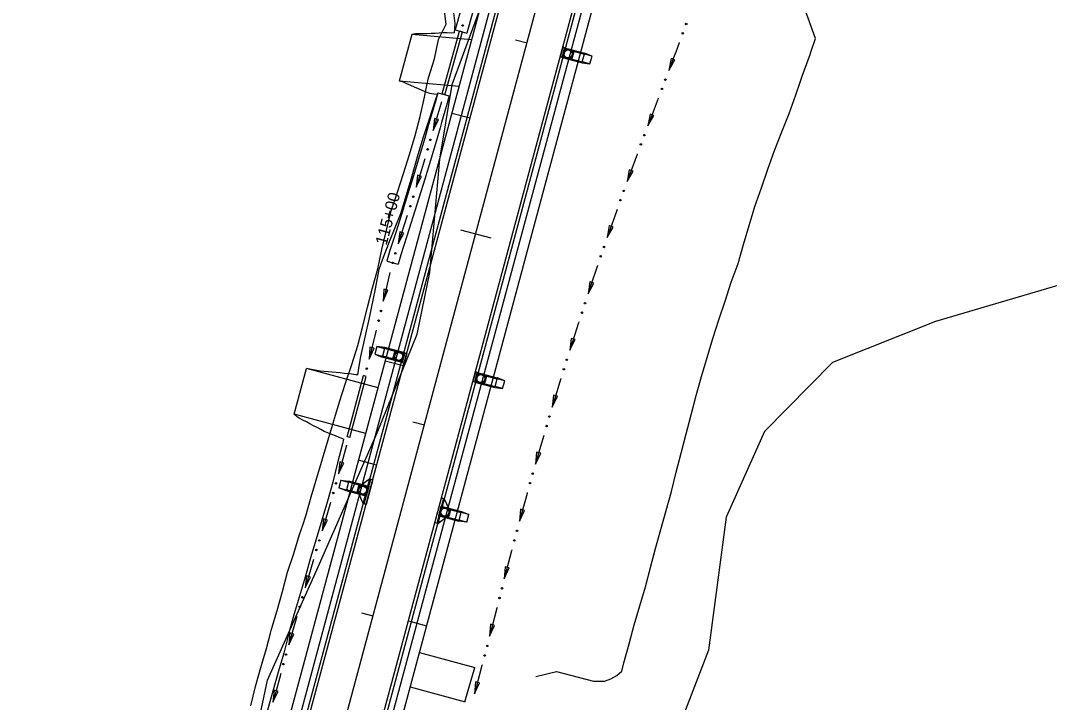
# Model space of a CAD drawing. Extents: x 979959 to 994833, y 1835619 to 1845316.
# Drawn here: x 992410 to 992930, y 1840093 to 1840438 of the extents above; entities that cross this region are included whole.
import ezdxf

# ---------------------------------------------------------------- set-up
doc = ezdxf.new("R2010")
doc.units = 0
for name, color, linetype in [('43', 7, 'Continuous'), ('Future 5 Lane Construction Limits', 7, 'Continuous'), ('R_Drainage', 7, 'Continuous'), ('R_Drainage Structure', 7, 'Continuous'), ('R_Horz Alg', 7, 'Continuous'), ('R_Horz Alg Stationing', 7, 'Continuous'), ('R_Proposed Const Limits', 7, 'Continuous'), ('R_Proposed Road', 7, 'Continuous'), ('R_Special Ditch', 7, 'Continuous')]:
    doc.layers.add(name, color=color, linetype=linetype)

msp = doc.modelspace()

# ---------------------------------------------------------------- linework, layer by layer
at = {"layer": '43'}
for points in [[(992621.79, 1840368.15), (992628.07, 1840405.79), (992643.68, 1840448.4), (992668.29, 1840487.44), (992720.39, 1840550.23), (992730.06, 1840577.03), (992737.54, 1840627.9), (992738.03, 1840675.61), (992735.39, 1840714.93), (992711.35, 1840789.79), (992657.1, 1840913.35), (992616.01, 1840968.75), (992554.37, 1841054.01), (992492.51, 1841112.85), (992422.69, 1841167.63), (992343.9, 1841218.47), (992195.05, 1841300.3), (992123.04, 1841334.73), (992016.5, 1841376.04), (991968.17, 1841403.44), (991911.14, 1841449.18)], [(993347.55, 1840512.83), (993212.6, 1840462.54), (993168.76, 1840438.22), (993078.36, 1840362.89), (993023.88, 1840330.57), (992872.5, 1840286.06), (992820.37, 1840265.31), (992785.96, 1840230.34), (992766.58, 1840187.1), (992757.72, 1840119.83), (992738.11, 1840069.09)], [(992517.56, 1840024.39), (992534.47, 1840104.68), (992560.81, 1840163.53), (992590.06, 1840229.67), (992610.27, 1840279.68), (992616.63, 1840310.73), (992621.79, 1840368.15)]]:
    msp.add_lwpolyline(points, dxfattribs=at)
at = {"layer": 'Future 5 Lane Construction Limits'}
for points in [[(992624.94, 1840436.39), (992624.94, 1840436.42), (992623.68, 1840446.93), (992623.26, 1840461.03), (992634.83, 1840462.41)], [(992526.13, 1840091.74), (992528.55, 1840101.44), (992531.16, 1840111.1), (992533.99, 1840120.69), (992536.1, 1840128.48), (992536.48, 1840129.88), (992536.61, 1840130.34), (992536.65, 1840130.5), (992536.78, 1840130.97), (992539.38, 1840139.95), (992542.13, 1840149.57), (992544.71, 1840159.23), (992547.79, 1840168.75), (992550.81, 1840178.3), (992552.36, 1840183.11), (992553.87, 1840187.83), (992556.68, 1840197.43), (992559.57, 1840207.01), (992562.44, 1840216.59), (992565.2, 1840226.2), (992568.07, 1840235.79), (992571.02, 1840245.35), (992574.07, 1840254.88), (992577.26, 1840264.38), (992580.29, 1840273.92), (992582.71, 1840283.63), (992585.12, 1840293.33), (992587.76, 1840302.98), (992590.34, 1840312.64), (992592.41, 1840322.44), (992594.73, 1840332.17), (992597.04, 1840341.91), (992600.27, 1840351.39), (992603.36, 1840360.92), (992606.33, 1840370.47), (992609.3, 1840380.03), (992611.77, 1840389.72), (992614, 1840399.48), (992614.69, 1840402.96), (992615.93, 1840409.31), (992619.07, 1840418.82), (992620.92, 1840427.77), (992621.1, 1840428.63), (992624.94, 1840436.39)]]:
    msp.add_lwpolyline(points, dxfattribs=at)
at = {"layer": 'R_Drainage'}
for p, q in [((992629.57, 1840433.49), (992635.35, 1840431.89)), ((992683.59, 1840419.58), (992684.88, 1840424.41)), ((992685.37, 1840424.28), (992683.92, 1840424.67)), ((992684.2, 1840419.93), (992685.24, 1840423.79)), ((992684.88, 1840424.41), (992695.02, 1840421.68)), ((992685.24, 1840423.79), (992694.89, 1840421.19)), ((992683.59, 1840419.58), (992693.72, 1840416.85)), ((992684.2, 1840419.93), (992693.85, 1840417.33)), ((992689.71, 1840423.11), (992688.41, 1840418.28)), ((992693.85, 1840417.33), (992694.89, 1840421.19)), ((992698.76, 1840420.15), (992694.89, 1840421.19)), ((992698.76, 1840420.15), (992695.02, 1840421.67)), ((992697.72, 1840416.29), (992698.76, 1840420.15)), ((992693.72, 1840416.85), (992697.72, 1840416.29)), ((992697.72, 1840416.29), (992693.85, 1840417.33)), ((992620.72, 1840401.7), (992626.5, 1840400.1)), ((992594.95, 1840316.58), (992600.74, 1840315.02)), ((992589.88, 1840273.41), (992588.84, 1840269.55)), ((992593.87, 1840272.85), (992589.88, 1840273.41)), ((992589.88, 1840273.41), (992593.74, 1840272.37)), ((992593.74, 1840272.37), (992592.7, 1840268.51)), ((992603.4, 1840269.77), (992593.74, 1840272.37)), ((992604.01, 1840270.13), (992593.87, 1840272.85)), ((992588.84, 1840269.55), (992592.57, 1840268.03)), ((992588.84, 1840269.55), (992592.7, 1840268.51)), ((992602.71, 1840265.3), (992592.57, 1840268.03)), ((992602.36, 1840265.91), (992592.7, 1840268.51)), ((992597.88, 1840266.6), (992599.18, 1840271.43)), ((992603.4, 1840269.77), (992602.36, 1840265.91)), ((992604.01, 1840270.13), (992602.71, 1840265.3)), ((992602.23, 1840265.43), (992603.67, 1840265.04)), ((992639.4, 1840255.42), (992640.7, 1840260.25)), ((992641.18, 1840260.12), (992639.74, 1840260.51)), ((992640.01, 1840255.77), (992641.05, 1840259.64)), ((992640.7, 1840260.25), (992650.84, 1840257.52)), ((992641.05, 1840259.64), (992650.71, 1840257.04)), ((992645.53, 1840258.95), (992644.23, 1840254.12)), ((992649.67, 1840253.17), (992650.71, 1840257.04)), ((992654.57, 1840256), (992650.71, 1840257.04)), ((992654.57, 1840256), (992650.84, 1840257.52)), ((992639.4, 1840255.42), (992649.54, 1840252.69)), ((992640.01, 1840255.77), (992649.67, 1840253.17)), ((992649.54, 1840252.69), (992653.53, 1840252.14)), ((992653.53, 1840252.14), (992649.67, 1840253.17)), ((992653.53, 1840252.14), (992654.57, 1840256)), ((992571.68, 1840205.82), (992570.64, 1840201.96)), ((992571.68, 1840205.82), (992575.54, 1840204.78)), ((992571.68, 1840205.82), (992575.68, 1840205.27)), ((992575.54, 1840204.78), (992574.5, 1840200.92)), ((992585.2, 1840202.18), (992575.54, 1840204.78)), ((992585.81, 1840202.53), (992575.68, 1840205.27)), ((992586.37, 1840206.52), (992581.27, 1840202.78)), ((992586.37, 1840206.52), (992582.24, 1840203.5)), ((992583.47, 1840193.84), (992586.85, 1840206.39)), ((992583.47, 1840193.84), (992586.85, 1840206.39)), ((992574.38, 1840200.44), (992570.64, 1840201.96)), ((992570.64, 1840201.96), (992574.5, 1840200.92)), ((992584.51, 1840197.7), (992574.38, 1840200.44)), ((992584.16, 1840198.32), (992574.5, 1840200.92)), ((992579.69, 1840199), (992580.99, 1840203.83)), ((992582.99, 1840193.97), (992580.46, 1840199.77)), ((992585.2, 1840202.18), (992584.16, 1840198.32)), ((992582.99, 1840193.97), (992580.94, 1840198.67)), ((992623.54, 1840196.54), (992620.16, 1840183.99)), ((992623.54, 1840196.52), (992620.18, 1840183.96)), ((992624.02, 1840196.41), (992626.56, 1840190.61)), ((992624.02, 1840196.39), (992626.08, 1840191.7)), ((992621.82, 1840188.18), (992622.86, 1840192.04)), ((992622.5, 1840192.66), (992632.64, 1840189.93)), ((992622.86, 1840192.04), (992632.52, 1840189.46)), ((992627.33, 1840191.38), (992626.03, 1840186.55)), ((992631.49, 1840185.6), (992632.52, 1840189.46)), ((992636.38, 1840188.43), (992632.52, 1840189.46)), ((992632.64, 1840189.93), (992636.38, 1840188.43)), ((992620.65, 1840183.86), (992625.74, 1840187.6)), ((992620.66, 1840183.83), (992624.78, 1840186.87)), ((992621.21, 1840187.82), (992631.35, 1840185.1)), ((992621.82, 1840188.18), (992631.49, 1840185.6)), ((992635.35, 1840184.56), (992631.35, 1840185.1)), ((992635.35, 1840184.56), (992631.49, 1840185.6)), ((992635.35, 1840184.56), (992636.38, 1840188.43))]:
    msp.add_line(p, q, dxfattribs=at)
for points in [[(992644, 1840484.65), (992634.47, 1840451.01), (992633.51, 1840447.61), (992633.1, 1840446.15), (992630.41, 1840436.51), (992629.57, 1840433.49)], [(992649.12, 1840480.73), (992640.24, 1840449.38), (992639.28, 1840445.99), (992638.87, 1840444.53), (992636.19, 1840434.9), (992635.35, 1840431.89)], [(992683.92, 1840424.67), (992682.62, 1840419.84), (992684.07, 1840419.45), (992685.37, 1840424.28)], [(992620.72, 1840401.7), (992619.67, 1840398), (992616.91, 1840388.39), (992616.09, 1840385.58), (992614.11, 1840378.81), (992611.26, 1840369.24), (992608.36, 1840359.67), (992605.42, 1840350.12), (992602.44, 1840340.59), (992599.4, 1840331.06), (992596.31, 1840321.48), (992594.95, 1840316.58)], [(992626.5, 1840400.1), (992625.44, 1840396.35), (992622.67, 1840386.73), (992621.85, 1840383.89), (992619.86, 1840377.11), (992617, 1840367.51), (992614.1, 1840357.92), (992611.15, 1840348.34), (992608.16, 1840338.78), (992605.12, 1840329.23), (992602.06, 1840319.75), (992600.74, 1840315.02)], [(992603.67, 1840265.04), (992604.97, 1840269.87), (992603.52, 1840270.26), (992602.23, 1840265.43)], [(992639.74, 1840260.51), (992638.44, 1840255.68), (992639.88, 1840255.29), (992641.18, 1840260.12)]]:
    msp.add_lwpolyline(points, dxfattribs=at)
for points in [[(992685.37, 1840424.28), (992684.07, 1840419.45), (992682.62, 1840419.84), (992683.92, 1840424.67)], [(992689.71, 1840423.11), (992688.41, 1840418.28), (992683.59, 1840419.58), (992684.88, 1840424.41)], [(992597.88, 1840266.6), (992599.18, 1840271.43), (992604.01, 1840270.13), (992602.71, 1840265.3)], [(992602.23, 1840265.43), (992603.52, 1840270.26), (992604.97, 1840269.87), (992603.67, 1840265.04)], [(992641.18, 1840260.12), (992639.89, 1840255.29), (992638.44, 1840255.68), (992639.74, 1840260.51)], [(992645.53, 1840258.95), (992644.23, 1840254.12), (992639.4, 1840255.42), (992640.7, 1840260.25)], [(992582.99, 1840193.97), (992586.37, 1840206.52), (992587.82, 1840206.13), (992584.44, 1840193.58)], [(992582.99, 1840193.97), (992586.37, 1840206.52), (992587.82, 1840206.13), (992584.44, 1840193.58)], [(992579.69, 1840199), (992580.99, 1840203.83), (992585.81, 1840202.53), (992584.51, 1840197.7)], [(992624.02, 1840196.41), (992620.65, 1840183.86), (992619.2, 1840184.25), (992622.58, 1840196.8)], [(992624.02, 1840196.39), (992620.66, 1840183.83), (992619.21, 1840184.22), (992622.57, 1840196.78)], [(992627.33, 1840191.38), (992626.03, 1840186.55), (992621.2, 1840187.85), (992622.5, 1840192.68)]]:
    msp.add_lwpolyline(points, close=True, dxfattribs=at)
for centre, radius in [((992686.65, 1840421.34), 2.5), ((992686.65, 1840421.34), 2.5), ((992686.65, 1840421.34), 2), ((992686.65, 1840421.34), 2), ((992600.94, 1840268.36), 2.5), ((992600.94, 1840268.36), 2.5), ((992600.94, 1840268.36), 2), ((992600.94, 1840268.36), 2), ((992642.47, 1840257.19), 2.5), ((992642.47, 1840257.19), 2.5), ((992642.47, 1840257.19), 2), ((992642.47, 1840257.19), 2), ((992582.75, 1840200.77), 2.5), ((992582.75, 1840200.77), 2.5), ((992582.75, 1840200.77), 2), ((992582.75, 1840200.77), 2), ((992624.27, 1840189.61), 2.5), ((992624.27, 1840189.61), 2.5), ((992624.27, 1840189.61), 2), ((992624.27, 1840189.61), 2)]:
    msp.add_circle(centre, radius, dxfattribs=at)
at = {"layer": 'R_Drainage Structure'}
for p, q in [((992622.88, 1840401.1), (992631.74, 1840432.89)), ((992624.32, 1840400.7), (992633.18, 1840432.49)), ((992633.18, 1840432.49), (992631.74, 1840432.89)), ((992624.32, 1840400.7), (992622.88, 1840401.1)), ((992574.84, 1840227.75), (992583.07, 1840258.67)), ((992576.29, 1840227.36), (992584.52, 1840258.29)), ((992584.52, 1840258.29), (992583.07, 1840258.67)), ((992576.29, 1840227.36), (992574.84, 1840227.75))]:
    msp.add_line(p, q, dxfattribs=at)
at = {"layer": 'R_Horz Alg'}
msp.add_line((992538.36, 1839953.12), (992767.08, 1840802.89), dxfattribs=at)
at = {"layer": 'R_Horz Alg Stationing'}
for points in [[(992660.09, 1840428.49), (992665.89, 1840426.93)], [(992632.17, 1840332.45), (992647.62, 1840328.29)], [(992608.11, 1840235.37), (992613.91, 1840233.81)], [(992582.12, 1840138.8), (992587.92, 1840137.24)]]:
    msp.add_lwpolyline(points, dxfattribs=at)
at = {"layer": 'R_Proposed Const Limits'}
for points in [[(992629.14, 1840431.95), (992629.43, 1840436.75), (992628, 1840449.06), (992628.03, 1840452.71), (992628.29, 1840457.77), (992638.27, 1840461.88), (992638.91, 1840469.13), (992640.19, 1840485.11), (992643.41, 1840505.48), (992647.52, 1840514.72), (992651.33, 1840524.05), (992655.17, 1840533.38), (992659.13, 1840542.67), (992662.71, 1840552.06), (992663.45, 1840554.83)], [(992811.82, 1840429.08), (992800.06, 1840462.04)], [(992629.14, 1840431.95), (992629.14, 1840431.95), (992627.47, 1840431.9), (992625.47, 1840432.01), (992623.47, 1840432.04), (992621.44, 1840431.83), (992619.41, 1840431.62), (992617.4, 1840431.59), (992615.39, 1840431.54), (992613.38, 1840431.51), (992611.37, 1840431.52), (992609.37, 1840431.54), (992607.57, 1840431.15)], [(992670.25, 1840106.53), (992680.84, 1840109.07), (992699.57, 1840104.22), (992705.08, 1840104.22), (992708.34, 1840105.37), (992711.31, 1840106.99), (992713.77, 1840109.28), (992714.92, 1840113.41), (992717.51, 1840123.07), (992720.1, 1840132.73), (992723, 1840142.31), (992725.76, 1840151.92), (992728.27, 1840161.6), (992730.91, 1840171.25), (992733.55, 1840180.89), (992736.23, 1840190.52), (992738.89, 1840200.17), (992741.33, 1840209.86), (992743.85, 1840219.54), (992746.34, 1840229.23), (992748.9, 1840238.9), (992751.49, 1840248.56), (992754.22, 1840258.17), (992757.02, 1840267.78), (992759.88, 1840277.36), (992762.97, 1840286.89), (992766.09, 1840296.4), (992769.23, 1840305.91), (992772.63, 1840315.36), (992775.33, 1840324.98), (992778.33, 1840334.53), (992780.31, 1840341.31), (992781.21, 1840344.11), (992784.43, 1840353.6), (992787.74, 1840363.07), (992791.15, 1840372.51), (992794.79, 1840381.88), (992798.44, 1840391.26), (992801.92, 1840400.68), (992802.41, 1840402.12), (992803.54, 1840405.47), (992805.17, 1840410.15), (992808.57, 1840419.6), (992808.68, 1840419.88), (992808.75, 1840420.08), (992809.66, 1840422.73), (992811.82, 1840429.08)], [(992620.58, 1840400.74), (992620.69, 1840400.73), (992618.71, 1840401.02), (992616.73, 1840401.31), (992614.78, 1840401.98), (992612.85, 1840402.83), (992610.91, 1840403.69), (992608.98, 1840404.54), (992607.05, 1840405.39), (992605.12, 1840406.24), (992603.31, 1840407.04), (992601.24, 1840407.61)], [(992580.21, 1840259.06), (992580.92, 1840263.4), (992581.85, 1840268.32), (992583.96, 1840278.11), (992586.24, 1840287.85), (992589.22, 1840302.59), (992591.04, 1840312.45), (992592.71, 1840317.18), (992596.32, 1840326.56), (992602, 1840340.57), (992604.88, 1840350.15), (992607.67, 1840359.76), (992610.48, 1840369.36), (992613.3, 1840378.95), (992616.47, 1840388.45), (992619.53, 1840397.99), (992620.58, 1840400.74)], [(992580.21, 1840259.06), (992579.31, 1840259.15), (992577.29, 1840259.36), (992575.28, 1840259.58), (992573.27, 1840259.82), (992571.28, 1840260.1), (992569.25, 1840260.26), (992567.22, 1840260.43), (992565.19, 1840260.59), (992563.17, 1840260.75), (992561.14, 1840260.91), (992554.26, 1840262.29)], [(992573.06, 1840226.56), (992572.65, 1840226.72), (992570.78, 1840227.46), (992568.9, 1840228.21), (992567.03, 1840228.95), (992565.16, 1840229.69), (992563.29, 1840230.43), (992561.48, 1840231.41), (992559.67, 1840232.37), (992557.86, 1840233.33), (992556.05, 1840234.29), (992554.23, 1840235.26), (992552.42, 1840236.22), (992550.61, 1840237.18), (992549.7, 1840237.66), (992548.02, 1840239.11)], [(992573.06, 1840226.56), (992572.48, 1840224.24), (992570, 1840214.55), (992567.53, 1840204.86), (992564.94, 1840195.21), (992561.97, 1840185.65), (992559.21, 1840176.04), (992556.25, 1840166.48), (992553.58, 1840156.84), (992550.75, 1840147.25), (992547.93, 1840137.65), (992545.23, 1840128.02), (992545.14, 1840127.7), (992544.99, 1840127.18), (992542.84, 1840118.31), (992540.01, 1840108.71), (992537.29, 1840099.09), (992534.53, 1840089.48), (992532.28, 1840079.73), (992530.58, 1840071.71), (992530.12, 1840069.95), (992527.96, 1840060.18), (992526.05, 1840050.34)]]:
    msp.add_lwpolyline(points, dxfattribs=at)
at = {"layer": 'R_Proposed Road'}
for p, q in [((992511.8, 1839960.26), (992691.67, 1840628.54)), ((992516.63, 1839958.96), (992696.9, 1840628.73)), ((992519.53, 1839958.18), (992699.8, 1840627.95)), ((992520.98, 1839957.79), (992701.25, 1840627.56)), ((992555.74, 1839948.44), (992713.43, 1840534.3)), ((992557.19, 1839948.05), (992714.88, 1840533.91)), ((992560.08, 1839947.27), (992717.77, 1840533.13)), ((992564.91, 1839945.97), (992722.6, 1840531.83)), ((992607.57, 1840431.15), (992601.24, 1840407.61)), ((992637.82, 1840428.47), (992607.57, 1840431.15)), ((992631.49, 1840404.93), (992601.24, 1840407.61)), ((992627.85, 1840391.41), (992637.02, 1840388.94)), ((992548.02, 1840239.11), (992554.26, 1840262.29)), ((992590.47, 1840252.54), (992554.26, 1840262.29)), ((992603.28, 1840263.59), (992594.11, 1840266.06)), ((992584.23, 1840229.37), (992548.02, 1840239.11)), ((992589.77, 1840213.38), (992580.59, 1840215.85)), ((992605.85, 1840134.62), (992615.02, 1840132.15)), ((992611.39, 1840118.63), (992639.39, 1840111.09)), ((992634.32, 1840093.82), (992639.39, 1840111.09)), ((992606.71, 1840101.25), (992634.52, 1840093.76))]:
    msp.add_line(p, q, dxfattribs=at)
at = {"layer": 'R_Special Ditch'}
for p, q in [((992738.74, 1840419.01), (992737.61, 1840413.02)), ((992737.61, 1840413.02), (992740.72, 1840418.26)), ((992740.72, 1840418.26), (992738.74, 1840419.01)), ((992619.03, 1840388.75), (992618.37, 1840382.69)), ((992618.37, 1840382.69), (992621.07, 1840388.16)), ((992621.07, 1840388.16), (992619.03, 1840388.75)), ((992728.1, 1840390.92), (992726.96, 1840384.93)), ((992726.96, 1840384.93), (992730.08, 1840390.17)), ((992730.08, 1840390.17), (992728.1, 1840390.92)), ((992717.56, 1840362.78), (992716.49, 1840356.78)), ((992716.49, 1840356.78), (992719.54, 1840362.05)), ((992719.54, 1840362.05), (992717.56, 1840362.78)), ((992610.48, 1840359.97), (992609.73, 1840353.92)), ((992609.73, 1840353.92), (992612.51, 1840359.35)), ((992612.51, 1840359.35), (992610.48, 1840359.97)), ((992601.53, 1840331.31), (992600.69, 1840325.28)), ((992600.69, 1840325.28), (992603.54, 1840330.66)), ((992603.54, 1840330.66), (992601.53, 1840331.31)), ((992707.4, 1840334.49), (992706.42, 1840328.48)), ((992706.42, 1840328.48), (992709.39, 1840333.8)), ((992709.39, 1840333.8), (992707.4, 1840334.49)), ((992697.63, 1840306.07), (992696.74, 1840300.04)), ((992696.74, 1840300.04), (992699.64, 1840305.4)), ((992699.64, 1840305.4), (992697.63, 1840306.07)), ((992593.43, 1840302.32), (992593.08, 1840296.24)), ((992593.08, 1840296.24), (992595.49, 1840301.83)), ((992595.49, 1840301.83), (992593.43, 1840302.32)), ((992688.27, 1840277.51), (992687.46, 1840271.48)), ((992690.28, 1840276.88), (992688.27, 1840277.51)), ((992586.39, 1840273.13), (992585.96, 1840267.05)), ((992585.96, 1840267.05), (992588.45, 1840272.62)), ((992588.45, 1840272.62), (992586.39, 1840273.13)), ((992687.46, 1840271.48), (992690.28, 1840276.88)), ((992679.3, 1840248.83), (992678.58, 1840242.78)), ((992678.58, 1840242.78), (992681.33, 1840248.22)), ((992681.33, 1840248.22), (992679.3, 1840248.83)), ((992571.1, 1840215.07), (992570.5, 1840209)), ((992573.14, 1840214.49), (992571.1, 1840215.07)), ((992670.74, 1840220.02), (992670.11, 1840213.96)), ((992670.11, 1840213.96), (992672.78, 1840219.44)), ((992672.78, 1840219.44), (992670.74, 1840220.02)), ((992570.5, 1840209), (992573.14, 1840214.49)), ((992662.59, 1840191.1), (992662.04, 1840185.03)), ((992662.04, 1840185.03), (992664.63, 1840190.54)), ((992664.63, 1840190.54), (992662.59, 1840191.1)), ((992562.85, 1840186.2), (992562.16, 1840180.15)), ((992562.16, 1840180.15), (992564.88, 1840185.6)), ((992564.88, 1840185.6), (992562.85, 1840186.2)), ((992654.84, 1840162.06), (992654.38, 1840155.99)), ((992654.38, 1840155.99), (992656.89, 1840161.54)), ((992656.89, 1840161.54), (992654.84, 1840162.06)), ((992554.26, 1840157.41), (992553.59, 1840151.36)), ((992553.59, 1840151.36), (992556.29, 1840156.82)), ((992556.29, 1840156.82), (992554.26, 1840157.41)), ((992647.44, 1840132.95), (992646.96, 1840126.88)), ((992646.96, 1840126.88), (992649.49, 1840132.42)), ((992649.49, 1840132.42), (992647.44, 1840132.95)), ((992545.89, 1840128.55), (992545.29, 1840122.49)), ((992545.29, 1840122.49), (992547.93, 1840127.98)), ((992547.93, 1840127.98), (992545.89, 1840128.55)), ((992639.81, 1840103.91), (992639.26, 1840097.84)), ((992639.26, 1840097.84), (992641.86, 1840103.36)), ((992641.86, 1840103.36), (992639.81, 1840103.91)), ((992537.85, 1840099.6), (992537.31, 1840093.53)), ((992537.31, 1840093.53), (992539.9, 1840099.05)), ((992539.9, 1840099.05), (992537.85, 1840099.6))]:
    msp.add_line(p, q, dxfattribs=at)
for points in [[(992742.88, 1840427.06), (992742.83, 1840426.93), (992741.09, 1840422.27), (992739.85, 1840418.96), (992739.31, 1840417.53), (992737.61, 1840413.02)], [(992742.89, 1840427.1), (992742.88, 1840427.06)], [(992732.28, 1840398.96), (992732.19, 1840398.73), (992728.63, 1840389.33), (992726.96, 1840384.93)], [(992732.29, 1840398.99), (992732.28, 1840398.96)], [(992622.53, 1840397.1), (992619.79, 1840387.56), (992618.97, 1840384.74), (992618.37, 1840382.69)], [(992622.54, 1840397.14), (992622.53, 1840397.1)], [(992614.1, 1840368.27), (992611.23, 1840358.8), (992609.73, 1840353.92)], [(992614.11, 1840368.31), (992614.1, 1840368.27)], [(992721.67, 1840370.86), (992721.55, 1840370.53), (992718.07, 1840361.11), (992717.06, 1840358.33), (992716.49, 1840356.78)], [(992721.68, 1840370.89), (992721.67, 1840370.86)], [(992711.4, 1840342.63), (992711.26, 1840342.23), (992707.92, 1840332.77), (992706.42, 1840328.48)], [(992711.41, 1840342.66), (992711.4, 1840342.63)], [(992605.26, 1840339.57), (992602.26, 1840330.14), (992600.69, 1840325.28)], [(992605.27, 1840339.6), (992605.26, 1840339.57)], [(992701.52, 1840314.26), (992701.37, 1840313.82), (992698.17, 1840304.33), (992696.74, 1840300.04)], [(992701.54, 1840314.3), (992701.52, 1840314.26)], [(992596.48, 1840310.84), (992594.26, 1840301.23), (992593.08, 1840296.24)], [(992596.49, 1840310.88), (992596.48, 1840310.85)], [(992692.04, 1840285.76), (992691.89, 1840285.31), (992688.83, 1840275.78), (992687.46, 1840271.48)], [(992692.05, 1840285.79), (992692.04, 1840285.76)], [(992589.57, 1840281.61), (992587.22, 1840272.06), (992587.22, 1840272.06), (992585.96, 1840267.05)], [(992589.58, 1840281.65), (992589.57, 1840281.61)], [(992682.96, 1840257.13), (992682.82, 1840256.68), (992679.89, 1840247.11), (992678.58, 1840242.78)], [(992682.97, 1840257.16), (992682.96, 1840257.13)], [(992674.29, 1840228.37), (992674.16, 1840227.94), (992671.36, 1840218.34), (992670.11, 1840213.96)], [(992674.3, 1840228.41), (992674.29, 1840228.37)], [(992574.52, 1840223.46), (992571.91, 1840214.04), (992570.5, 1840209)], [(992574.53, 1840223.49), (992574.52, 1840223.46)], [(992666.01, 1840199.49), (992665.9, 1840199.1), (992663.24, 1840189.46), (992662.04, 1840185.03)], [(992666.02, 1840199.53), (992666.01, 1840199.49)], [(992566.38, 1840194.54), (992563.65, 1840185.2), (992562.16, 1840180.15)], [(992566.39, 1840194.58), (992566.38, 1840194.54)], [(992658.15, 1840170.5), (992658.05, 1840170.14), (992655.53, 1840160.47), (992654.38, 1840155.99)], [(992658.16, 1840170.54), (992658.15, 1840170.5)], [(992557.84, 1840165.74), (992555.08, 1840156.44), (992553.59, 1840151.36)], [(992557.86, 1840165.78), (992557.84, 1840165.74)], [(992549.4, 1840136.96), (992549.39, 1840136.92)], [(992650.68, 1840141.41), (992650.6, 1840141.08), (992648.13, 1840131.39), (992646.96, 1840126.88)], [(992650.69, 1840141.45), (992650.68, 1840141.41)], [(992549.39, 1840136.92), (992546.73, 1840127.62), (992546.64, 1840127.3), (992546.49, 1840126.78), (992545.29, 1840122.49)], [(992643.15, 1840112.33), (992643.07, 1840112.04), (992640.49, 1840102.38), (992640.41, 1840102.06), (992639.26, 1840097.84)], [(992643.16, 1840112.37), (992643.15, 1840112.33)], [(992541.25, 1840108), (992538.71, 1840098.71), (992537.31, 1840093.53)], [(992541.26, 1840108.04), (992541.25, 1840108)]]:
    msp.add_lwpolyline(points, dxfattribs=at)
for centre in [(992633.33, 1840435.69), (992746.4, 1840436.46), (992744.66, 1840431.76), (992735.87, 1840408.32), (992734.1, 1840403.64), (992617, 1840377.88), (992725.22, 1840380.24), (992615.57, 1840373.08), (992723.46, 1840375.55), (992714.82, 1840352.06), (992608.29, 1840349.13), (992713.13, 1840347.34), (992606.79, 1840344.35), (992599.19, 1840320.5), (992703.19, 1840319), (992704.81, 1840323.74), (992597.85, 1840315.68), (992695.2, 1840295.28), (992591.96, 1840291.36), (992693.64, 1840290.52), (992590.78, 1840286.49), (992584.77, 1840262.19), (992684.49, 1840261.91), (992685.99, 1840266.69), (992677.17, 1840237.98), (992675.75, 1840233.17), (992667.41, 1840204.32), (992668.77, 1840209.14), (992567.8, 1840199.36), (992569.17, 1840204.18), (992660.76, 1840180.19), (992560.77, 1840175.34), (992659.47, 1840175.35), (992559.32, 1840170.54), (992653.17, 1840151.13), (992552.21, 1840146.55), (992651.94, 1840146.27), (992550.82, 1840141.73), (992645.74, 1840122.02), (992543.97, 1840117.66), (992644.46, 1840117.18), (992542.63, 1840112.83)]:
    msp.add_circle(centre, 0.375, dxfattribs=at)

# ---------------------------------------------------------------- texts
at = {"layer": 'R_Horz Alg Stationing'}
msp.add_text('115+00', height=6, rotation=74.9354, dxfattribs=at).set_placement((992594.76, 1840324.25))

doc.saveas('drawing.dxf')
